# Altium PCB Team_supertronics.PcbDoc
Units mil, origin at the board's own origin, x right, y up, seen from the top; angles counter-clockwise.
Board outline 3543.31 x 3543.31 mil, 2 copper layers (Top Layer, Bottom Layer); 15 components, 14 nets, 105 pads, 14 vias.
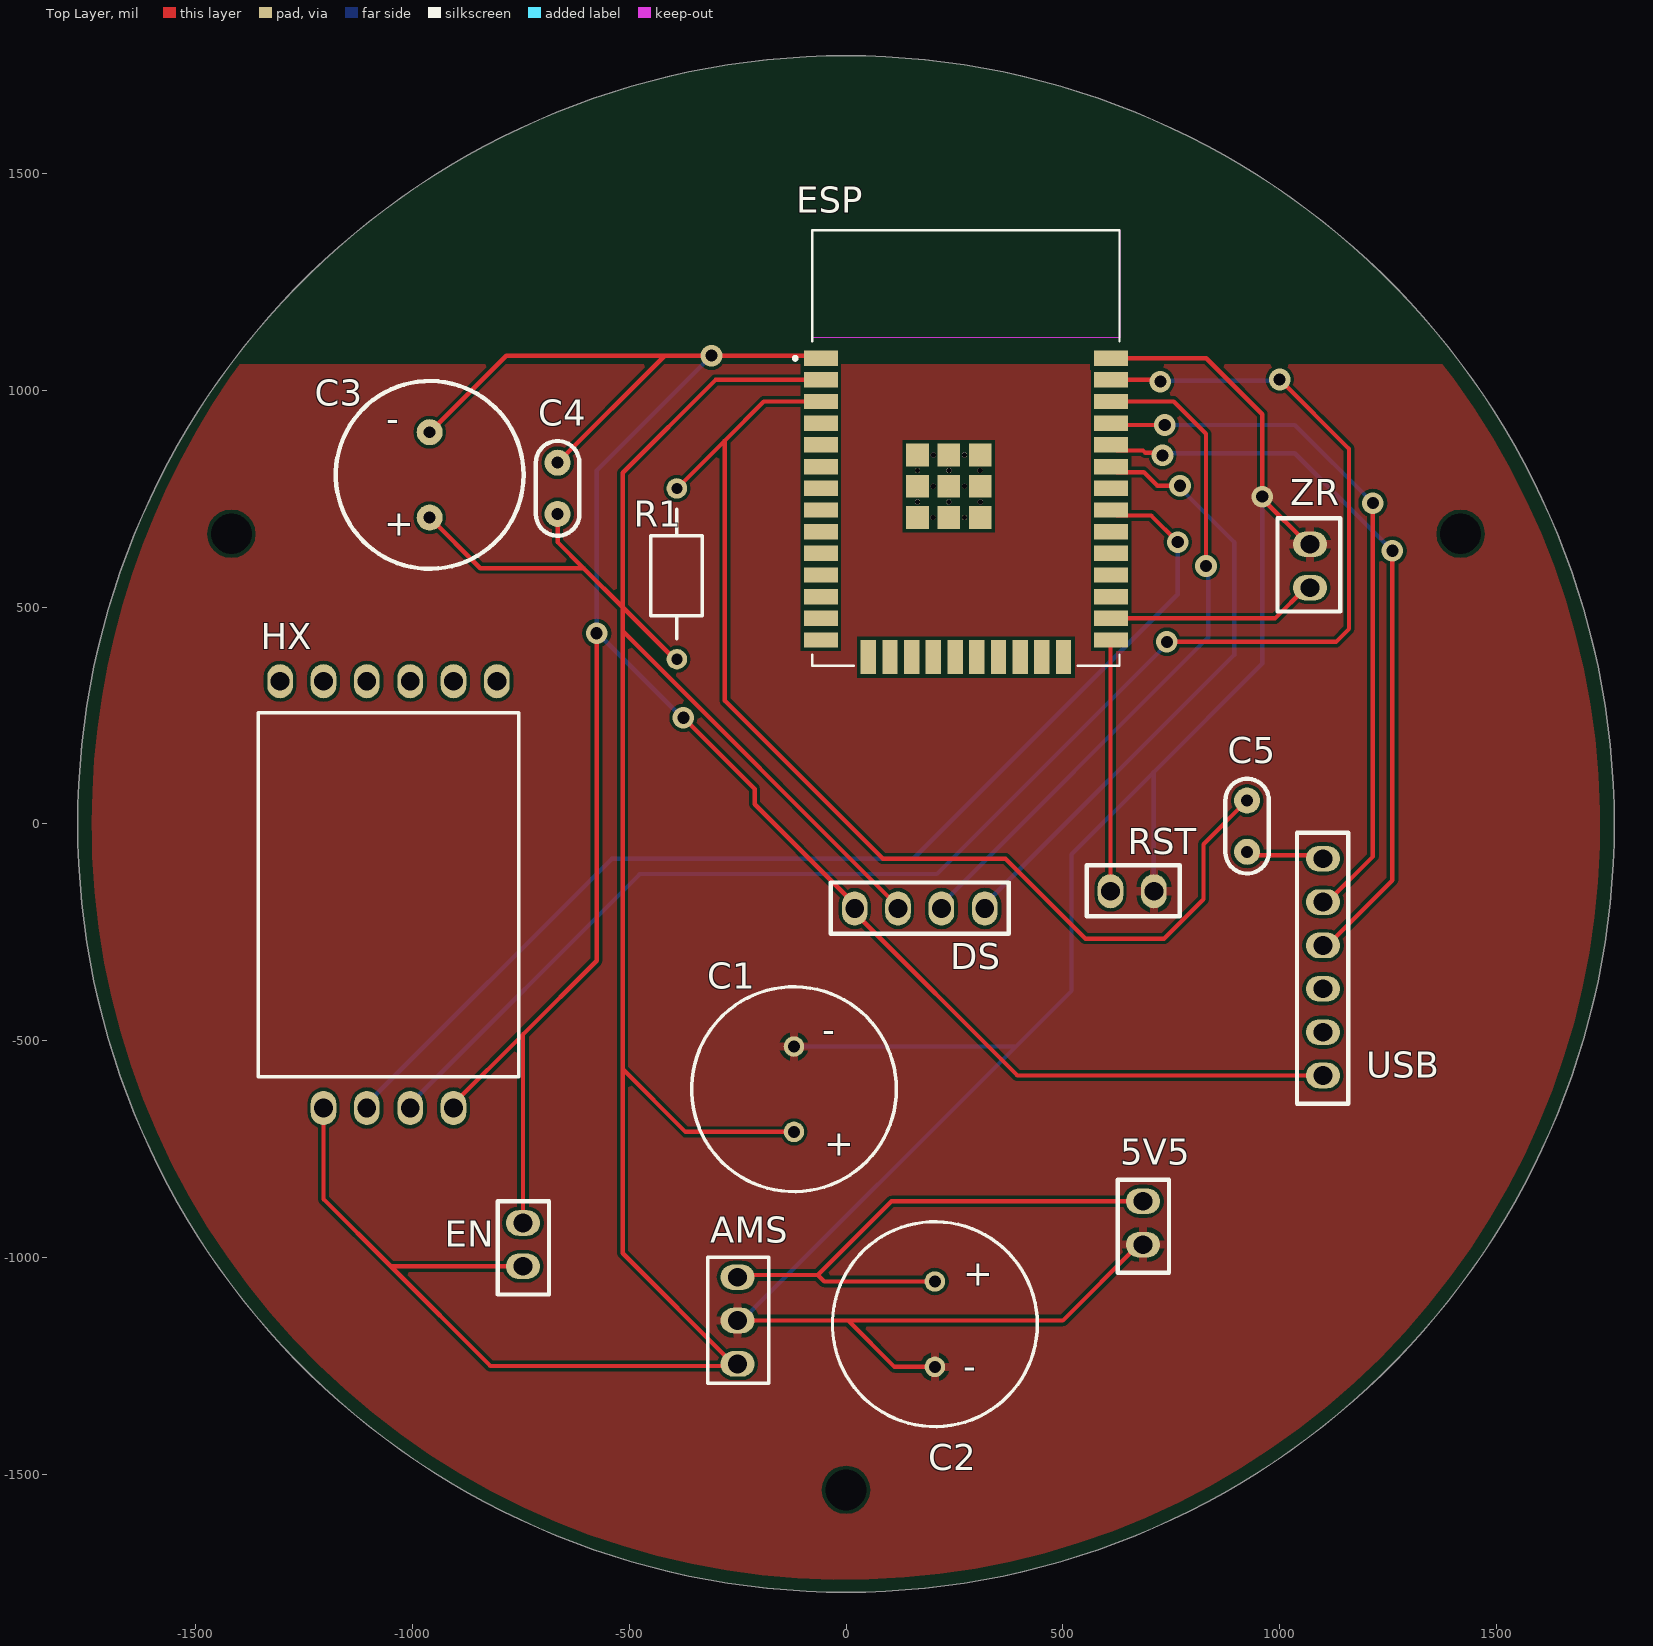
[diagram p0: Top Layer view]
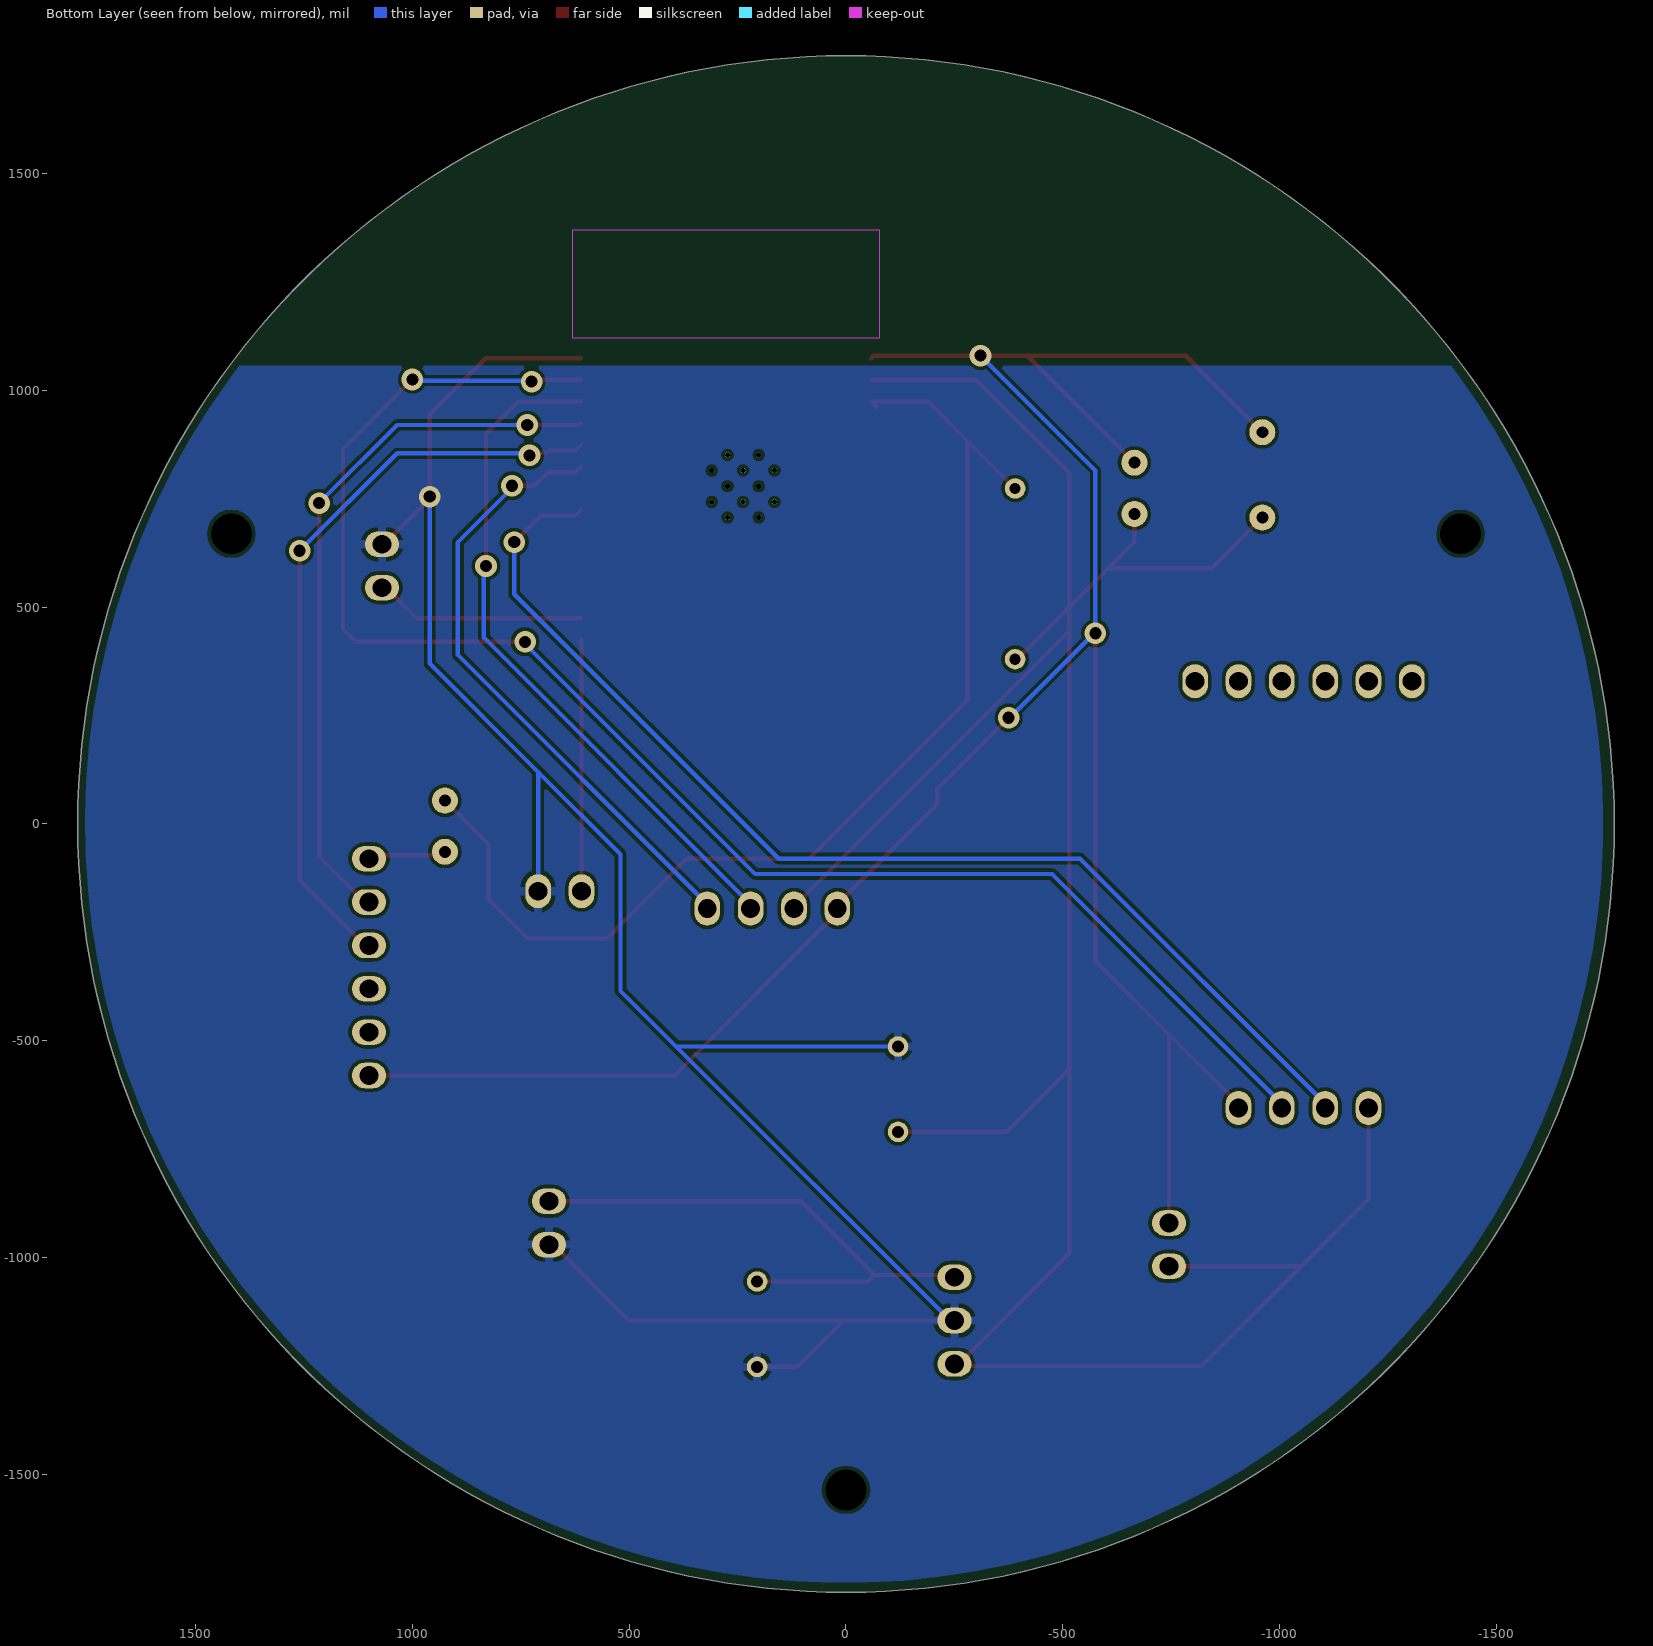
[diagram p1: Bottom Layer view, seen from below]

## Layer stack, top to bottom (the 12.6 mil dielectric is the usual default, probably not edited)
Top Solder: solder mask 0.4, Solder Resist, Dk 3.5
Top Layer: signal copper 1.4
Dielectric 1: dielectric 12.6, FR-4, Dk 4.8
Bottom Layer: signal copper 1.4
Bottom Solder: solder mask 0.4, Solder Resist, Dk 3.5

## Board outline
-1771.65,0 ccw(c0,0) 0,-1771.65 ccw(c0,0) 1771.65,0 ccw(c0,0) 0,1771.65 ccw(c0,0)

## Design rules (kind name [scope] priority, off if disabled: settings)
BoardOutlineClearance [All] p1: gap=11.81 ignorepadtopadclearanceinfootprint=FALSE except(15.75: Arc-SplitBarrior Arc-SplitContinuation Track-SplitBarrior Track-SplitContinuation SMDPad-SplitBarrior SMDPad-SplitContinuation THPad-SplitBarrior THPad-SplitContinuation Via-SplitBarrior Via-SplitContinuation Fill-SplitBarrior Fill-SplitContinuation Poly-SplitBarrior Poly-SplitContinuation Region-SplitBarrior Region-SplitContinuation Text-SplitBarrior Text-SplitContinuation)
Clearance "Clearance Different Nets" [All] p1: gap=7.87 ignorepadtopadclearanceinfootprint=FALSE except(3.5: Arc-Arc Arc-Track Arc-SMDPad Track-Track Track-SMDPad; 5: SMDPad-SMDPad SMDPad-Via THPad-Via Via-Via; 10: Arc-Via Arc-Text Track-Via Track-Text SMDPad-Text THPad-Text Via-Text Fill-Text Poly-Text Region-Text Text-Text; 19.68: THPad-THPad Via-Hole)
Clearance "Clearance Same Nets" [All] p2: gap=7.87 ignorepadtopadclearanceinfootprint=FALSE except(3.5: Arc-Arc Arc-Track Arc-SMDPad Track-Track Track-SMDPad SMDPad-SMDPad; 5: SMDPad-Via THPad-Via; 10: Arc-Via Arc-Text Track-Via Track-Text SMDPad-Text THPad-Text Via-Via Via-Text Fill-Text Poly-Text Region-Text Text-Text)
Clearance "Clearance Bottom Layer" [OnLayer('Bottom Layer')] p3: gap=8 ignorepadtopadclearanceinfootprint=TRUE except(10: Arc-Text Track-Text SMDPad-Text THPad-Text Via-Text Fill-Text Poly-Text Region-Text Text-Text)
Clearance "Clearance Top Layer" [OnLayer('Top Layer')] p4: gap=8 ignorepadtopadclearanceinfootprint=TRUE except(10: Arc-Text Track-Text SMDPad-Text THPad-Text Via-Text Fill-Text Poly-Text Region-Text Text-Text)
HoleSize [All] p1: absolutevalues=TRUE maxlimit=248.03 minlimit=7.87 maxpercent=80.000 minpercent=20.000
MinimumAnnularRing [All] p1: minimumring=5.12
MinimumSolderMaskSliver [All] p1: minsoldermaskwidth=3.94
PolygonConnect PolygonConnect_1 [All] p1: thpad.connectstyle=Relief thpad.reliefconductorwidth=20 thpad.reliefentries=4 thpad.polygonreliefangle="90 Angle" thpad.airgapwidth=10 smdpad.connectstyle=Relief smdpad.reliefconductorwidth=20 smdpad.reliefentries=4 smdpad.polygonreliefangle="90 Angle" smdpad.airgapwidth=10 via.connectstyle=Direct via.reliefconductorwidth=20 via.reliefentries=4 via.polygonreliefangle="90 Angle" via.airgapwidth=10
RoutingCorners [All] p1: cornerstyle=Round minsetback=100 maxsetback=100
RoutingVias [All] p1: holewidth=19.68 width=39.37 viastyle="Through Hole" minholewidth=7.87 minwidth=13.78 maxholewidth=39.37 maxwidth=78.74
SilkToSilkClearance [All] p1: silktosilkclearance=3.94
SilkToSolderMaskClearance [IsPad] p1: minsilkscreentomaskgap=3.94 clearancetoexposedcopper=TRUE
SolderMaskExpansion [All] p1: expansion=4 istentingtop=FALSE
Width [All] p1: maxlimit=100 minlimit=3.5 preferedwidth=15
25 further rules are at their usual default settings.

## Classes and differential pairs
component class Sheet1: 5V5 AMS C1 C2 C3 C4 C5 DS EN ESP R1 RST USB ZR

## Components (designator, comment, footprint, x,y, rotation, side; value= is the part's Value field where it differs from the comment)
5V5 "5V" 5V5 140,-770 r0 top
AMS "AMS1117-3.3S" AMS1117-3.3s -250,-1045 r0 top
C1 "Capacitor_16ZLJ470MTA8X11.5" Cap_470_16z -165,-590 r90 top
C2 "470uF_cap" 470uF_Capacitor 205,-1055 r270 top
C3 "Capacitor_10uF" 10uF_Capacitor -960,805 r90 top
C4 "Capacitor_0.1uF" Cap_0.1uF -505,159.06 r90 top
C5 "2_Capacitor_0.1uF" 0.1uF_Capacitor 925,-5 r90 top
DS "Digital_screen" Digital_screen -305,3665 r270 top
EN "EN_push_button" EN_push_button -4550,915 r0 top
ESP "ESP32_WROOM_32D" ESP32_WROOM32D 4921.61,19782.07 r0 top
HX "HX711" HX711 -805,329.25 r270 top
R1 "Resistor_10k" 10K_ohm_resistor -390,380 r90 top
RST "Reset_push_button" Reset_push_button 659.9,-2569.99 r90 top
USB "USB_port" USB_port -2760,-705 r0 top
ZR "zero_push_button" Zero_push_button 3485.04,595.01 r180 top

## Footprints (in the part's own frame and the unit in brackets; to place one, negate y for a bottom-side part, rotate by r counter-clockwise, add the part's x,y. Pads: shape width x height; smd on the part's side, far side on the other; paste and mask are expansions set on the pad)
0.1uF_Capacitor [mil]
  round 60 hole 27.56: 76(-59.05,0) 77(59.06,0)
  silkscreen extent -109,-50 109,50
5V5 [mm]
  oval 2x1.5 hole 1.1: 80(13.843,-2.54) 81(13.843,-5.08)
  silkscreen extent 12.37,-6.73 15.37,-1.27
10K_ohm_resistor [mm] "Resistor"
  round 1.2 hole 0.65: 58(0,0) 59(10,0)
  silkscreen extent 1.2,-1.48 8.8,1.52
10uF_Capacitor [mil]
  round 60 hole 27.56: 56(-98.43,0) 57(98.43,0)
  silkscreen extent -216,-217 216,216
470uF_Capacitor [mm] "470 µF 16 V Aluminum Electrolytic Capacitors Radial, Can 9000 Hrs @ 105°C"
  round 1.2 hole 0.7: 78(0,0) 79(5,0)
  silkscreen extent -3.5,-6 8.5,6
AMS1117-3.3s [mm]
  oval 2x1.5 hole 1.1: 3(0,0) 4(0,-5.08) 5(0,-2.54)
  silkscreen extent -1.75,-6.22 1.83,1.17
Cap_0.1uF [mil]
  round 60 hole 27.56: 54(555.94,160) 55(674.05,160)
  silkscreen extent 506,110 724,210
Cap_470_16z [mm]
  round 1.2 hole 0.7: 1(-3.048,-1.143) 2(1.952,-1.143)
  silkscreen extent -6.55,-7.14 5.45,4.85
Digital_screen [mm] "Screen"
  oval 2x1.5 hole 1.1: 72(98.044,15.875) 73(98.044,13.335) 74(98.044,10.795) 75(98.044,8.255)
  silkscreen extent 96.52,6.86 99.52,17.27
EN_push_button [mm] "EN"
  oval 2x1.5 hole 1.1: 62(96.647,-46.609) 63(96.647,-49.149)
  silkscreen extent 95.17,-50.8 98.17,-45.34
ESP32_WROOM32D [mm]
  rect 2x0.9 smd: 16(-126.483,-475.181) 17(-126.483,-476.451) 18(-126.483,-477.721) 19(-126.483,-478.991) 20(-126.483,-480.261) 21(-126.483,-481.531) 22(-126.483,-482.801) 23(-126.483,-484.071) 24(-126.483,-485.341) 25(-126.483,-486.611) 26(-126.483,-487.881) 27(-126.483,-489.151) 28(-126.483,-490.421) 29(-126.483,-491.691) 40(-109.483,-491.691) 41(-109.483,-490.421) 42(-109.483,-489.151) 43(-109.483,-487.881) 44(-109.483,-486.611) 45(-109.483,-485.341) 46(-109.483,-484.071) 47(-109.483,-482.801) 48(-109.483,-481.531) 49(-109.483,-480.261) 50(-109.483,-478.991) 51(-109.483,-477.721) 52(-109.483,-476.451) 53(-109.483,-475.181)
  rect 0.9x2 smd: 30(-123.698,-492.691) 31(-122.428,-492.691) 32(-121.158,-492.691) 33(-119.888,-492.691) 34(-118.618,-492.691) 35(-117.348,-492.691) 36(-116.078,-492.691) 37(-114.808,-492.691) 38(-113.538,-492.691) 39(-112.268,-492.691)
  rect 1.33x1.33 smd: 39_1(-120.818,-480.846) 39_2(-118.983,-480.846) 39_3(-117.148,-480.846) 39_4(-120.818,-482.681) 39_5(-118.983,-482.681) 39_6(-117.148,-482.681) 39_7(-120.818,-484.516) 39_8(-118.983,-484.516) 39_9(-117.148,-484.516)
  round 0.3 hole 0.3 unplated: 39_10(-119.9,-480.846) 39_11(-118.065,-480.846) 39_12(-120.818,-481.763) 39_13(-118.983,-481.763) 39_14(-117.148,-481.763) 39_15(-119.9,-482.681) 39_16(-118.065,-482.681) 39_17(-120.818,-483.598) 39_18(-118.983,-483.598) 39_19(-117.148,-483.598) 39_20(-119.9,-484.516) 39_21(-118.065,-484.516)
  Keep-Out Layer region: -108.983,-473.991 -126.983,-473.991 -126.983,-467.691 -108.983,-467.691
  silkscreen extent -128.08,-493.19 -108.98,-467.69, body extent -126.98,-493.19 -108.98,-467.69, height 3.25
HX711 [mm]
  oval 2x1.5 hole 1.1: 6(0,0) 7(0,-2.54) 8(0,-5.08) 9(0,-7.62) 10(0,-10.16) 11(0,-12.7) 12(25,-2.54) 13(25,-5.08) 14(25,-7.62) 15(25,-10.16)
  silkscreen extent 1.84,-13.97 23.17,1.27
Reset_push_button [mm] "Reset"
  oval 2x1.5 hole 1.1: 60(61.341,1.268) 61(61.341,-1.272)
  silkscreen extent 59.86,-2.79 62.86,2.67
USB_port [mm] "USB"
  oval 2x1.5 hole 1.1: 66(98.044,15.875) 67(98.044,13.335) 68(98.044,10.795) 69(98.044,8.255) 70(98.044,5.715) 71(98.044,3.175)
  silkscreen extent 96.52,1.52 99.52,17.4
Zero_push_button [mm] "Zero"
  oval 2x1.5 hole 1.1: 64(61.342,1.27) 65(61.342,-1.27)
  silkscreen extent 59.56,-2.79 63.25,2.67

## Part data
AMS: "Linear Voltage Regulator IC Positive Fixed 1 Output 1A SOT-89"
C1 C2: "470 µF 16 V Aluminum Electrolytic Capacitors Radial, Can 9000 Hrs @ 105°C"
C3: "10uF"
C4: "0.1uF"
EN: "EN"
R1: "10kOhm"
RST: "Reset"
ZR: "Zero"

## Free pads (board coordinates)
  round 60 hole 94.49 unplated: 100(1417.32,669.29) 101(-1417.32,669.29) 102(0,-1535.43)

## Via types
v1: diameter 50, hole 28, Top Layer to Bottom Layer, 14 vias

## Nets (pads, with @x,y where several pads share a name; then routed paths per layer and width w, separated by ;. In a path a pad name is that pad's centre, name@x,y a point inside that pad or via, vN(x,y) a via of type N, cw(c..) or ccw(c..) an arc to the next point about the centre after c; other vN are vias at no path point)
Net5V5_80: 5V5.80 AMS.3 C2.78 | length 1283.7
  Top Layer w10: AMS.3 -245,-1040 -65,-1040 ; C2.78 -50,-1055 -65,-1040 ; 5V5.80 105,-870 -65,-1040
Net5V5_81: 5V5.81 AMS.5 C1.2 C2.79 ESP.53 RST.61 ZR.65 | length 5196.1
  Top Layer w10: AMS.5 5,-1145 ; C2.79 111.85,-1251.85 5,-1145 ; ESP.53 830.85,1074.15 960,945 960,750.08 1065.08,645 ZR.65 ; 5V5.81 675.16,-970 500.16,-1145 5,-1145
  Bottom Layer w10: AMS.5 -240.16,-1145 391.69,-513.15 ; C1.2 391.69,-513.15 ; RST.61 710,120 ; v1(960,755) 960,370 710,120 ; 391.69,-513.15 520,-384.84 520,-70 710,120
NetAMS_4: AMS.4 C1.1 C3.56 C4.54 DS.74 EN.63 ESP.17 HX.15 R1.58 | length 6544
  Top Layer w10: HX.15 -1205,-865 -1050,-1020 ; C3.56 -843.43,590 -605,590 ; EN.63 -1050,-1020 ; C4.54 -665,650 -605,590 ; R1.58 -395,380 -515,500 ; AMS.4@-259.84,-1245 -515,-989.84 -515,-565 ; AMS.4@-255,-1250 -820,-1250 -1050,-1020 ; C1.1 -370,-710 -515,-565 ; ESP.17 -300.85,1024.15 -515,810 -515,500 ; DS.74 120,-190 -515,445 ; -605,590 -515,500 ; -515,-565 -515,445 ; -515,445 -515,500
"NetC3_ 57": C3.57 C4.55 DS.75 EN.62 ESP.16 HX.12 USB.71 | length 5879.7
  Top Layer w10: C3.57 -783.43,1080 -418.11,1080 ; HX.12 -905,-645.16 -745,-485.16 ; EN.62 -745,-485.16 ; C4.55 -418.11,1080 ; v1@-580,445 v1(-575,440) -575,-315.16 -745,-485.16 ; v1(-375,245) -210.66,80.66 -210.66,45.5 20,-185.16 DS.75 20,-204.84 395.16,-580 USB.71 ; ESP.16 -63.88,1080 v1(-310,1080) -418.11,1080
  Bottom Layer w10: v1(-375,245) -377.5,245 -572.5,440 v1(-575,440) -575,815 v1(-310,1080)
NetC5_76: C5.76 USB.66 | length 181.6
  Top Layer w10: C5.76 932.97,-72.03 1092.03,-72.03 USB.66
NetC5_77: C5.77 ESP.18 R1.59 | length 2670.8
  Top Layer w10: R1.59 -279.35,884.35 ; ESP.18@-70.75,961.44 ESP.18 -189.55,974.15 -279.35,884.35 ; C5.77 824.44,-46.51 824.44,-173.38 733.44,-264.37 552.19,-264.37 367.82,-80 85,-80 -279.35,284.35 -279.35,884.35
NetDS_72: DS.72 ESP.48 | length 1442
  Top Layer w10: ESP.48 623.98,811.44 686.68,811.44 718.12,780 v1(770,780)
  Bottom Layer w10: DS.72 320,-185.16 895,389.84 895,650 770,775 v1(770,780)
NetDS_73: DS.73 ESP.51 | length 1601.3
  Top Layer w10: ESP.51 755.85,974.15 830,900 v1(830,595)
  Bottom Layer w10: DS.73 220,-185.16 835,429.84 835,590 v1(830,595)
NetESP_40: ESP.40 RST.60 | length 585
  Top Layer w10: RST.60 610,422.89 ESP.40 ESP.40@615,420.41
NetESP_41: ESP.41 ZR.64 | length 488.1
  Top Layer w10: ESP.41 989.31,474.15 1060.16,545 ZR.64
NetESP_46: ESP.46 HX.14 | length 2661.1
  Top Layer w10: ESP.46 623.98,711.44 703.56,711.44 v1(765,650)
  Bottom Layer w10: HX.14 -1105,-645.16 -539.84,-80 155,-80 765,530 v1@765,640
NetESP_49: ESP.49 USB.68 | length 1736.1
  Top Layer w10: ESP.49 623.98,861.44 685,861.44 690,856.44 723.56,856.44 v1(730,850) ; USB.68 1109.84,-280 1260,-129.84 v1(1260,630)
  Bottom Layer w10: v1(730,850) 735,855 1035,855 v1(1260,630)
NetESP_50: ESP.50 USB.67 | length 1653.5
  Top Layer w10: ESP.50 615.41,920 v1(735,920) ; USB.67 1109.84,-180 1215,-74.84 v1(1215,740)
  Bottom Layer w10: v1@745,935 745,928.48 753.48,920 1035,920 v1(1215,740)
NetESP_52: ESP.52 HX.13 | length 3629.7
  Top Layer w10: ESP.52 709.15,1024.15 v1@710,1025 ; v1(740,420) 1130,420 1160,450 1160,865 v1(1000,1025)
  Bottom Layer w10: HX.13 -1005,-645.16 -475.23,-115.39 209.61,-115.39 v1@730,405 ; v1(725,1020) 727.5,1022.5 997.5,1022.5 v1(1000,1025)
pads on no net: ESP.19 ESP.20 ESP.21 ESP.22 ESP.23 ESP.24 ESP.25 ESP.26 ESP.27 ESP.28 ESP.29 ESP.30 ESP.31 ESP.32 ESP.33 ESP.34 ESP.35 ESP.36 ESP.37 ESP.38 ESP.39 ESP.39_1 ESP.39_2 ESP.39_3 ESP.39_4 ESP.39_5 ESP.39_6 ESP.39_7 ESP.39_8 ESP.39_9 ESP.39_10 ESP.39_11 ESP.39_12 ESP.39_13 ESP.39_14 ESP.39_15 ESP.39_16 ESP.39_17 ESP.39_18 ESP.39_19 ESP.39_20 ESP.39_21 ESP.42 ESP.43 ESP.44 ESP.45 ESP.47 HX.6 HX.7 HX.8 HX.9 HX.10 HX.11 USB.69 USB.70

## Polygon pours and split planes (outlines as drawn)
Net5V5_81 on Bottom Layer "2" (solid, pour order 8): -1745,0 ccw(c4.43,0) 1398.76,1056.58 -1395.51,1056.58 ccw(c1.63,8.35)
Net5V5_81 on Top Layer "Top Layer-Net5V5_81" (solid, pour order 10): -1738.33,-33.33 ccw(c-0.08,-3.73) 1375,1060 -1398.48,1060 ccw(c77.36,1.77)

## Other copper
Top Layer:
  pour cut-out: -1376.83,1105 1376.83,1105 ccw(c0,-9.94)

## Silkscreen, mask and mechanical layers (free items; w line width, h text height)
Top Overlay:
  text "-" at -1060,905.01 h60
  text "+" at -1065,665 h60
  text "-" at -55,-504.99 h60
  text "+" at -50,-765 h60
  text "+" at 270,-1065 h60
  text "-" at 270,-1279.99 h60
